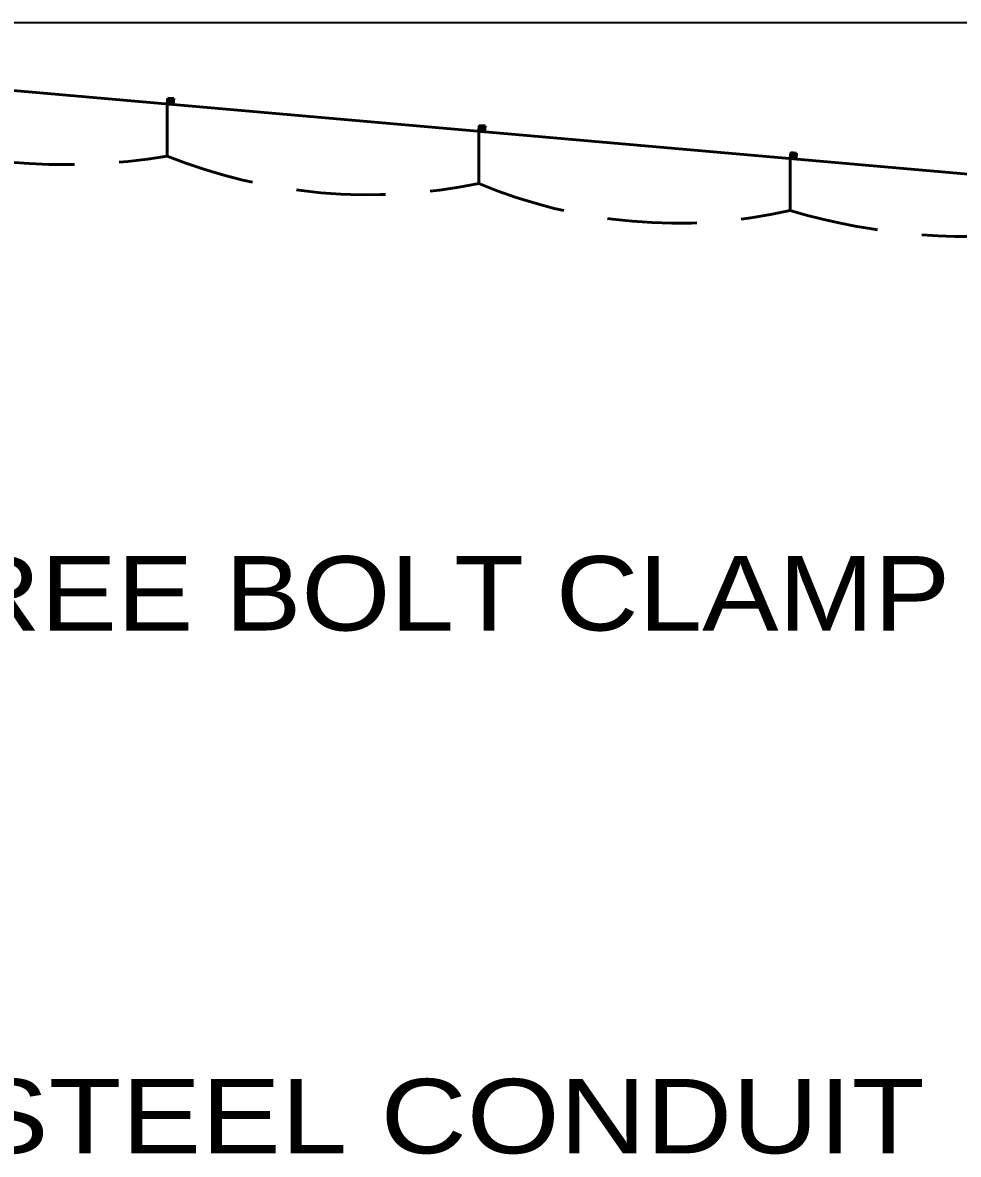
# Model space of a CAD drawing. Extents: x 12366 to 13046, y 9129 to 9570.
# Drawn here: x 12490.24 to 12521.67, y 9467.46 to 9505.48 of the extents above; entities that cross this region are included whole.
import ezdxf

# ---------------------------------------------------------------- set-up
doc = ezdxf.new("R2010")
doc.units = 0
doc.linetypes.add('MEDIUM_DASHED', pattern=[4.5, 3, -1.5])
doc.layers.add('1', color=7, linetype='Continuous', lineweight=53)

msp = doc.modelspace()

# ---------------------------------------------------------------- linework, layer by layer
at = {"layer": '1', "lineweight": 35}
msp.add_line((12476.534, 9505.477), (12560.545, 9505.477), dxfattribs=at)
at = {"layer": '1'}
for p, q in [((12487.527, 9503.403), (12523.636, 9500.244)), ((12495.115, 9502.94), (12495.098, 9502.741)), ((12495.111, 9502.89), (12495.098, 9502.741)), ((12495.098, 9502.741), (12495.247, 9502.728)), ((12495.098, 9502.741), (12495.098, 9500.991)), ((12495.098, 9502.741), (12495.297, 9502.724)), ((12495.129, 9502.939), (12495.111, 9502.74)), ((12495.111, 9502.89), (12495.26, 9502.877)), ((12495.124, 9502.889), (12495.111, 9502.74)), ((12495.115, 9502.94), (12495.314, 9502.923)), ((12495.144, 9502.938), (12495.126, 9502.739)), ((12495.139, 9502.888), (12495.126, 9502.739)), ((12495.159, 9502.937), (12495.141, 9502.737)), ((12495.154, 9502.887), (12495.141, 9502.737)), ((12495.174, 9502.935), (12495.156, 9502.736)), ((12495.17, 9502.885), (12495.156, 9502.736)), ((12495.182, 9502.935), (12495.164, 9502.735)), ((12495.192, 9502.934), (12495.175, 9502.734)), ((12495.188, 9502.884), (12495.175, 9502.734)), ((12495.204, 9502.933), (12495.186, 9502.733)), ((12495.199, 9502.883), (12495.186, 9502.733)), ((12495.215, 9502.932), (12495.197, 9502.732)), ((12495.223, 9502.931), (12495.205, 9502.732)), ((12495.218, 9502.881), (12495.205, 9502.732)), ((12495.238, 9502.93), (12495.22, 9502.73)), ((12495.234, 9502.88), (12495.22, 9502.73)), ((12495.253, 9502.928), (12495.235, 9502.729)), ((12495.248, 9502.878), (12495.235, 9502.729)), ((12495.265, 9502.927), (12495.247, 9502.728)), ((12495.26, 9502.877), (12495.247, 9502.728)), ((12495.275, 9502.926), (12495.258, 9502.727)), ((12495.285, 9502.925), (12495.268, 9502.726)), ((12495.295, 9502.925), (12495.278, 9502.725)), ((12495.305, 9502.924), (12495.288, 9502.724)), ((12495.314, 9502.923), (12495.297, 9502.724)), ((12505.575, 9502.025), (12505.558, 9501.826)), ((12505.571, 9501.975), (12505.558, 9501.826)), ((12505.589, 9502.024), (12505.571, 9501.825)), ((12505.571, 9501.975), (12505.72, 9501.962)), ((12505.584, 9501.974), (12505.571, 9501.825)), ((12505.575, 9502.025), (12505.774, 9502.008)), ((12505.604, 9502.023), (12505.586, 9501.823)), ((12505.6, 9501.973), (12505.586, 9501.823)), ((12505.619, 9502.021), (12505.601, 9501.822)), ((12505.615, 9501.971), (12505.601, 9501.822)), ((12505.634, 9502.02), (12505.617, 9501.821)), ((12505.63, 9501.97), (12505.617, 9501.821)), ((12505.642, 9502.019), (12505.624, 9501.82)), ((12505.653, 9502.019), (12505.635, 9501.819)), ((12505.648, 9501.969), (12505.635, 9501.819)), ((12505.664, 9502.017), (12505.646, 9501.818)), ((12505.659, 9501.968), (12505.646, 9501.818)), ((12505.675, 9502.016), (12505.657, 9501.817)), ((12505.683, 9502.016), (12505.665, 9501.817)), ((12505.679, 9501.966), (12505.665, 9501.816)), ((12505.698, 9502.014), (12505.681, 9501.815)), ((12505.694, 9501.965), (12505.681, 9501.815)), ((12505.713, 9502.013), (12505.695, 9501.814)), ((12505.708, 9501.963), (12505.695, 9501.814)), ((12505.725, 9502.012), (12505.707, 9501.813)), ((12505.72, 9501.962), (12505.707, 9501.813)), ((12505.735, 9502.011), (12505.718, 9501.812)), ((12505.745, 9502.01), (12505.728, 9501.811)), ((12505.755, 9502.009), (12505.738, 9501.81)), ((12505.765, 9502.008), (12505.748, 9501.809)), ((12505.774, 9502.008), (12505.757, 9501.808)), ((12505.558, 9501.826), (12505.707, 9501.813)), ((12505.558, 9501.826), (12505.558, 9500.076)), ((12505.558, 9501.826), (12505.757, 9501.808)), ((12516.035, 9501.11), (12516.018, 9500.911)), ((12516.031, 9501.06), (12516.018, 9500.911)), ((12516.018, 9500.911), (12516.167, 9500.898)), ((12516.018, 9500.911), (12516.018, 9499.161)), ((12516.018, 9500.911), (12516.217, 9500.893)), ((12516.049, 9501.109), (12516.031, 9500.91)), ((12516.031, 9501.06), (12516.18, 9501.047)), ((12516.044, 9501.059), (12516.031, 9500.91)), ((12516.035, 9501.11), (12516.235, 9501.092)), ((12516.064, 9501.108), (12516.047, 9500.908)), ((12516.06, 9501.058), (12516.047, 9500.908)), ((12516.079, 9501.106), (12516.062, 9500.907)), ((12516.075, 9501.056), (12516.062, 9500.907)), ((12516.094, 9501.105), (12516.077, 9500.906)), ((12516.09, 9501.055), (12516.077, 9500.906)), ((12516.102, 9501.104), (12516.084, 9500.905)), ((12516.113, 9501.103), (12516.095, 9500.904)), ((12516.108, 9501.053), (12516.095, 9500.904)), ((12516.124, 9501.102), (12516.106, 9500.903)), ((12516.12, 9501.052), (12516.106, 9500.903)), ((12516.135, 9501.101), (12516.117, 9500.902)), ((12516.143, 9501.101), (12516.126, 9500.901)), ((12516.139, 9501.051), (12516.126, 9500.901)), ((12516.158, 9501.099), (12516.141, 9500.9)), ((12516.154, 9501.049), (12516.141, 9500.9)), ((12516.173, 9501.098), (12516.155, 9500.899)), ((12516.169, 9501.048), (12516.155, 9500.899)), ((12516.185, 9501.097), (12516.167, 9500.898)), ((12516.18, 9501.047), (12516.167, 9500.898)), ((12516.196, 9501.096), (12516.178, 9500.897)), ((12516.205, 9501.095), (12516.188, 9500.896)), ((12516.215, 9501.094), (12516.198, 9500.895)), ((12516.225, 9501.093), (12516.208, 9500.894)), ((12516.235, 9501.092), (12516.217, 9500.893))]:
    msp.add_line(p, q, dxfattribs=at)
at = {"layer": '1', "linetype": 'MEDIUM_DASHED'}
for centre, radius, start, end in [((12491.648, 9521.905), 21.196, 250.6292, 279.3671), ((12501.845, 9517.874), 18.181, 248.2157, 281.784), ((12512.218, 9515.968), 17.231, 247.2606, 282.7391), ((12522.053, 9519.668), 21.377, 253.6022, 277.6499)]:
    msp.add_arc(centre, radius, start, end, dxfattribs=at)

# ---------------------------------------------------------------- texts
at = {"layer": '1'}
for s, width, p in [('THREE BOLT CLAMP', 1.15, (12482.94, 9485.055)), ('1 1/4" STEEL CONDUIT', 1.2, (12476.975, 9467.491))]:
    msp.add_text(s, height=2.5, dxfattribs=dict(at, width=width)).set_placement(p)

doc.saveas('drawing.dxf')
